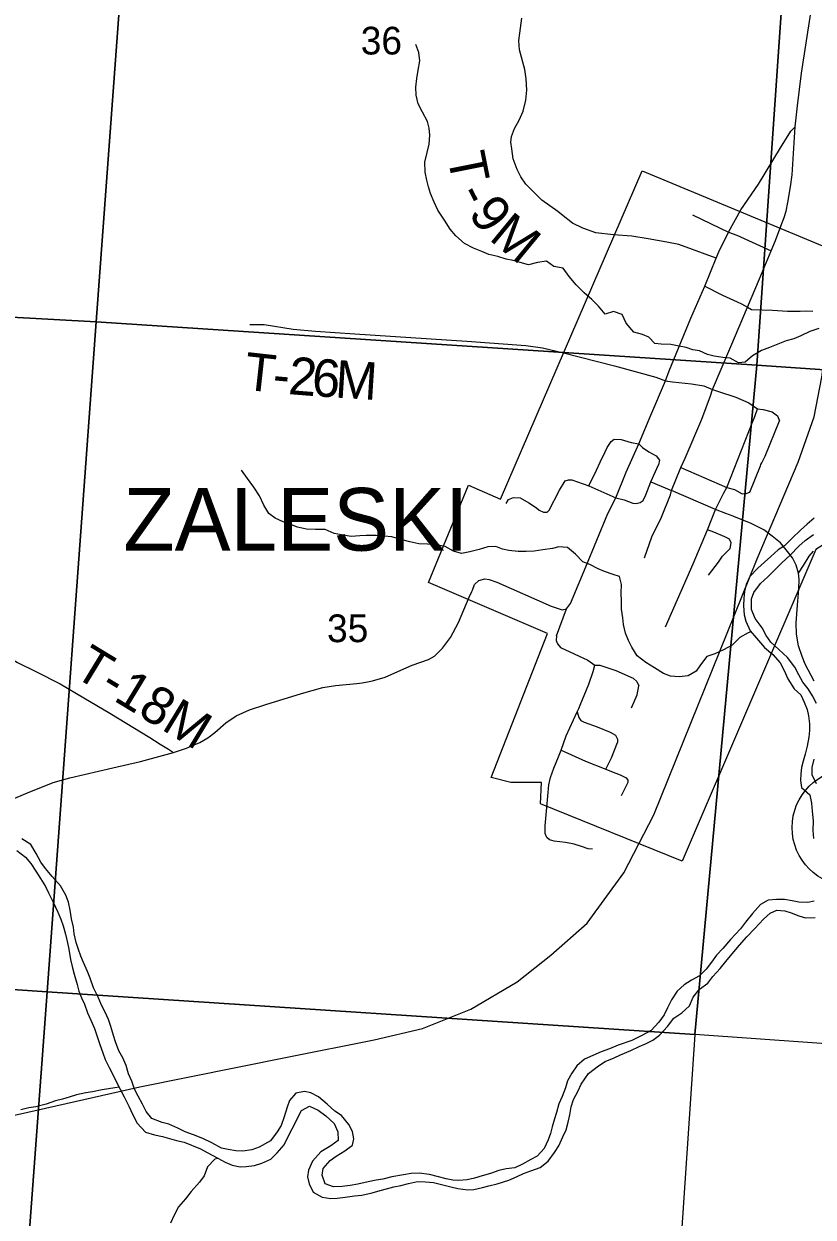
# Model space of a CAD drawing. Extents: x 0 to 34, y 0 to 22.
# Drawn here: x 26.642 to 27.834, y 16.59 to 18.393 of the extents above; entities that cross this region are included whole.
import ezdxf

# ---------------------------------------------------------------- set-up
doc = ezdxf.new("R2010")
doc.units = 0
for name, color, linetype in [('GM_X_City_Street', 7, 'Continuous'), ('GM_X_Corporation', 7, 'Continuous'), ('GM_X_Corporation_Text', 7, 'Continuous'), ('GM_X_Major_River', 7, 'Continuous'), ('GM_X_Minor_River', 7, 'Continuous'), ('GM_X_Rail_Line', 7, 'Continuous'), ('GM_X_Section', 7, 'Continuous'), ('GM_X_Section_Text', 7, 'Continuous'), ('GM_X_State_Route', 7, 'Continuous'), ('GM_X_Township_Road', 7, 'Continuous'), ('GM_X_Township_Road_Text', 7, 'Continuous'), ('SH_Data', 7, 'Continuous')]:
    doc.layers.add(name, color=color, linetype=linetype)

msp = doc.modelspace()

# ---------------------------------------------------------------- linework, layer by layer
at = {"layer": 'GM_X_City_Street'}
for p, q in [((27.5892, 17.7005), (27.6008, 17.7263)), ((27.4467, 17.4681), (27.4618, 17.5091))]:
    msp.add_line(p, q, dxfattribs=at)
for points in [[(27.5364, 17.6767), (27.552, 17.7153), (27.5708, 17.758), (27.5889, 17.8016), (27.6112, 17.8534), (27.6169, 17.8683), (27.6497, 17.9479), (27.6705, 17.9964), (27.688, 18.0388), (27.6918, 18.048), (27.7064, 18.078), (27.725, 18.1115)], [(27.6519, 18.104), (27.7064, 18.078), (27.7191, 18.0733), (27.7709, 18.0497)], [(27.6705, 17.9964), (27.6973, 17.9828), (27.7193, 17.9729), (27.7259, 17.9695)], [(27.7259, 17.9695), (27.7352, 17.9647), (27.7414, 17.9612), (27.7731, 17.96), (27.7954, 17.9585), (27.8148, 17.9588), (27.8244, 17.959), (27.8338, 17.9588)], [(27.5344, 17.876), (27.5966, 17.8591), (27.6112, 17.8534), (27.6221, 17.8517), (27.6507, 17.849), (27.669, 17.8457), (27.6824, 17.84), (27.6913, 17.8373), (27.7173, 17.8286), (27.7369, 17.8202), (27.7501, 17.8108), (27.7587, 17.81), (27.7724, 17.8063), (27.7803, 17.8004), (27.7833, 17.7929)], [(27.6115, 17.4818), (27.6531, 17.577), (27.6745, 17.6283), (27.6868, 17.6591), (27.6992, 17.6839), (27.7037, 17.6923), (27.7426, 17.7909), (27.7461, 17.7996), (27.7501, 17.8108)], [(27.7554, 17.7267), (27.7567, 17.7293), (27.7617, 17.7396), (27.7833, 17.7929)], [(27.4957, 17.6948), (27.5069, 17.7186), (27.5126, 17.7305), (27.5203, 17.7461), (27.5232, 17.7528), (27.5294, 17.7619)], [(27.5294, 17.7619), (27.5339, 17.7652), (27.5443, 17.7647), (27.5594, 17.7602), (27.5708, 17.758), (27.5768, 17.7528), (27.5862, 17.7463), (27.5971, 17.7401), (27.6021, 17.7337), (27.6008, 17.7263)], [(27.6345, 17.7225), (27.7037, 17.6923), (27.7154, 17.6891), (27.727, 17.6824), (27.733, 17.6829), (27.7384, 17.6851)], [(27.7384, 17.6851), (27.7546, 17.725), (27.7554, 17.7267)], [(27.3707, 17.6682), (27.3743, 17.6742), (27.3817, 17.6769), (27.3919, 17.6764), (27.405, 17.6692), (27.4164, 17.6613), (27.4206, 17.6578), (27.4271, 17.6549), (27.4325, 17.6551), (27.4357, 17.6578), (27.4511, 17.6883), (27.46, 17.7025), (27.4647, 17.7039), (27.4699, 17.7037), (27.4957, 17.6948), (27.5364, 17.6767)], [(27.5795, 17.5857), (27.5907, 17.6177), (27.6051, 17.6476), (27.6189, 17.6811), (27.6202, 17.6878)], [(27.6764, 17.5597), (27.6911, 17.5793), (27.6976, 17.5886), (27.7087, 17.6001), (27.7104, 17.6088), (27.7077, 17.614), (27.701, 17.6177), (27.6841, 17.6246), (27.6745, 17.6283)], [(27.4467, 17.4681), (27.4463, 17.4609), (27.4482, 17.4562), (27.4528, 17.4505), (27.494, 17.4311), (27.5048, 17.4239)], [(27.4321, 17.2087), (27.4353, 17.2429), (27.4374, 17.2539), (27.4427, 17.2682), (27.4496, 17.2851), (27.4539, 17.2951), (27.4612, 17.317), (27.4781, 17.3532), (27.4805, 17.3584), (27.4822, 17.3631), (27.4955, 17.3952), (27.5022, 17.414), (27.5048, 17.4239)], [(27.5048, 17.4239), (27.5122, 17.4237), (27.5362, 17.4157), (27.5624, 17.4039), (27.5679, 17.399), (27.5711, 17.3925)], [(27.5599, 17.3595), (27.5683, 17.3789), (27.5711, 17.3925)], [(27.4781, 17.3532), (27.4803, 17.3447), (27.4834, 17.3401), (27.4885, 17.3377), (27.5081, 17.3306), (27.5278, 17.3223), (27.5356, 17.3181), (27.5386, 17.3118), (27.5386, 17.3071)], [(27.4539, 17.2951), (27.4906, 17.2786), (27.5214, 17.2666), (27.5295, 17.263), (27.5426, 17.2579), (27.5517, 17.2537), (27.5546, 17.2501), (27.5544, 17.2465), (27.5445, 17.2262)], [(27.5214, 17.2666), (27.5299, 17.2839), (27.5386, 17.3071)]]:
    msp.add_lwpolyline(points, dxfattribs=at)
at = {"layer": 'GM_X_Corporation'}
msp.add_lwpolyline([(27.6365, 17.1274), (27.4226, 17.2144), (27.4242, 17.2466), (27.3779, 17.2466), (27.3482, 17.2539), (27.433, 17.4716), (27.2534, 17.5487), (27.314, 17.6957), (27.362, 17.6745), (27.5761, 18.1708), (28.0217, 17.9852), (27.9273, 17.6794), (27.9105, 17.6553), (27.8801, 17.6232), (27.8492, 17.6058), (27.8383, 17.5985)], close=True, dxfattribs=at)
at = {"layer": 'GM_X_Major_River'}
for points in [[(27.8356, 17.646), (27.8253, 17.6366), (27.8153, 17.6276), (27.8027, 17.6155), (27.7909, 17.6042), (27.7814, 17.5978), (27.7703, 17.5881), (27.7608, 17.5794), (27.7505, 17.5704), (27.7386, 17.5576), (27.7332, 17.5455), (27.7305, 17.5352), (27.7297, 17.525), (27.7292, 17.5132), (27.7303, 17.5), (27.7325, 17.4901)], [(27.7955, 17.4354), (27.7823, 17.4472), (27.7706, 17.4587), (27.7635, 17.4686), (27.7575, 17.4804), (27.7469, 17.4945), (27.7413, 17.5078), (27.7414, 17.5238), (27.7445, 17.5336), (27.7549, 17.5472), (27.7656, 17.557), (27.7774, 17.569), (27.7869, 17.5785), (27.7995, 17.5901), (27.8125, 17.6033), (27.8221, 17.612), (27.8346, 17.6214)], [(27.7325, 17.4901), (27.7392, 17.4756), (27.7486, 17.4645), (27.7607, 17.4504), (27.7735, 17.4397), (27.7844, 17.4271), (27.7904, 17.4157), (27.796, 17.4031), (27.8058, 17.3878), (27.8156, 17.3787), (27.8208, 17.368), (27.8253, 17.357), (27.8271, 17.3471), (27.8286, 17.3349), (27.8285, 17.3251), (27.8277, 17.3152), (27.8253, 17.3012), (27.8222, 17.2895), (27.8191, 17.2789), (27.8168, 17.269), (27.8156, 17.2595), (27.8151, 17.2497), (27.8169, 17.2387), (27.8294, 17.2279), (27.8316, 17.215), (27.833, 17.2032), (27.8341, 17.1888), (27.834, 17.174), (27.835, 17.1619)], [(27.8394, 17.3656), (27.8334, 17.3774), (27.8267, 17.3881), (27.8188, 17.398), (27.8128, 17.409), (27.8068, 17.4208), (27.7955, 17.4354)], [(27.8394, 17.2446), (27.8326, 17.2583), (27.8327, 17.2693), (27.8358, 17.2818)], [(27.1743, 16.6458), (27.1625, 16.6432), (27.1469, 16.6395), (27.1352, 16.6377), (27.123, 16.6363), (27.1097, 16.6357), (27.0972, 16.6399), (27.0928, 16.6532), (27.0944, 16.6631), (27.1047, 16.6755), (27.1142, 16.6819), (27.1272, 16.6902), (27.1386, 16.6984), (27.1406, 16.7083), (27.1384, 16.7193), (27.1331, 16.73), (27.1222, 16.7433), (27.112, 16.7498), (27.1003, 16.7605), (27.0875, 16.7716), (27.0758, 16.7774), (27.0663, 16.7794), (27.053, 16.7772), (27.0435, 16.7659), (27.04, 16.7561), (27.0353, 16.7413), (27.0311, 16.7284), (27.0249, 16.7186), (27.015, 16.705), (26.9979, 16.6953), (26.9864, 16.6916), (26.9728, 16.6894), (26.9622, 16.6899), (26.9508, 16.6918), (26.9406, 16.6938), (26.9262, 16.7023), (26.9126, 16.7084), (26.8986, 16.7139), (26.8861, 16.7189), (26.8751, 16.7243), (26.8615, 16.7301), (26.8513, 16.7328), (26.8358, 16.739), (26.8268, 16.7493), (26.8215, 16.7603), (26.8152, 16.7725), (26.8092, 16.7832), (26.8054, 16.795), (26.8006, 16.8064), (26.7969, 16.8189), (26.7916, 16.8304), (26.7856, 16.841), (26.7808, 16.8547), (26.7778, 16.8642), (26.7737, 16.8779), (26.77, 16.8886), (26.7652, 16.8996), (26.7595, 16.9103), (26.7547, 16.9221), (26.7476, 16.9362), (26.7424, 16.951), (26.7383, 16.9609), (26.7323, 16.9746), (26.7285, 16.9841), (26.7248, 16.994), (26.7215, 17.0047), (26.7185, 17.018), (26.7171, 17.0278), (26.7145, 17.0404), (26.7123, 17.0537), (26.7097, 17.0658), (26.7056, 17.0765), (26.6978, 17.0902), (26.685, 17.1043), (26.6748, 17.1166), (26.668, 17.1261), (26.6609, 17.139), (26.653, 17.1528), (26.6391, 17.1616)], [(26.6317, 17.1438), (26.645, 17.1338), (26.6529, 17.1239), (26.6604, 17.1125), (26.6675, 17.1014), (26.675, 17.0892), (26.6795, 17.0797), (26.6866, 17.0656), (26.6937, 17.0504), (26.6982, 17.0401), (26.7015, 17.0298), (26.7053, 17.0173), (26.7082, 17.0044), (26.7104, 16.9945), (26.713, 16.9789), (26.7152, 16.9683), (26.7181, 16.9569), (26.7226, 16.9413), (26.7255, 16.9314), (26.7293, 16.9211), (26.7338, 16.9116), (26.7382, 16.8987), (26.7435, 16.8876), (26.7491, 16.8747), (26.7524, 16.864), (26.7569, 16.8507), (26.7617, 16.8378), (26.7651, 16.8279), (26.7714, 16.8157), (26.7767, 16.8054), (26.7827, 16.7929), (26.7879, 16.783), (26.7939, 16.7715), (26.8014, 16.7563), (26.8063, 16.7456), (26.8137, 16.7319), (26.8258, 16.7182), (26.8394, 16.7143), (26.8515, 16.7115), (26.8625, 16.7088), (26.8731, 16.7057), (26.8845, 16.703), (26.9091, 16.6929), (26.9193, 16.6875), (26.9352, 16.6787), (26.9465, 16.6729), (26.9571, 16.6683), (26.9688, 16.6659), (26.9783, 16.6662), (26.9905, 16.6676), (27.0019, 16.6714), (27.0152, 16.6773), (27.0251, 16.6867), (27.0354, 16.6992), (27.0412, 16.7105), (27.0473, 16.723), (27.0616, 16.751), (27.0737, 16.7573), (27.087, 16.7515), (27.0983, 16.7431), (27.1111, 16.7313), (27.1163, 16.7187), (27.117, 16.7058), (27.106, 16.6975), (27.0907, 16.6885), (27.0781, 16.6742), (27.0723, 16.6606), (27.0708, 16.6507), (27.073, 16.6401), (27.0793, 16.6275), (27.0926, 16.6202), (27.1058, 16.6182), (27.1157, 16.6185)], [(27.8359, 17.067), (27.826, 17.0652), (27.8128, 17.0657), (27.8025, 17.0676), (27.7908, 17.0696), (27.779, 17.0697), (27.7665, 17.0687), (27.7547, 17.0623), (27.7425, 17.0487), (27.7322, 17.0355), (27.7245, 17.0253), (27.7096, 17.0091), (27.6978, 16.9959), (27.6882, 16.9854), (27.6809, 16.9752), (27.6725, 16.9646), (27.6626, 16.9545), (27.6504, 16.9477), (27.6394, 16.941), (27.6291, 16.9312), (27.6206, 16.9183), (27.6145, 16.9059), (27.6091, 16.8957), (27.6014, 16.8843), (27.5896, 16.8719), (27.5755, 16.864), (27.5603, 16.8569), (27.5398, 16.8495), (27.5268, 16.8443), (27.5143, 16.8395), (27.5014, 16.8342), (27.4892, 16.8286), (27.4773, 16.8185), (27.4697, 16.8075), (27.4635, 16.7958), (27.4604, 16.7852), (27.455, 16.772), (27.4504, 16.761), (27.4469, 16.7481), (27.4438, 16.7383), (27.4399, 16.7262), (27.4376, 16.7163), (27.4341, 16.7065), (27.428, 16.6933), (27.4173, 16.6819), (27.4078, 16.6767), (27.3952, 16.67), (27.3838, 16.6644), (27.3709, 16.6626), (27.3595, 16.6604), (27.3469, 16.6559), (27.3344, 16.6522), (27.323, 16.6489), (27.312, 16.6463), (27.2994, 16.6453), (27.29, 16.6457), (27.2801, 16.6477), (27.2684, 16.6508), (27.2547, 16.6543), (27.2392, 16.6563), (27.2274, 16.6556), (27.2157, 16.6535), (27.1978, 16.6506), (27.1845, 16.6472), (27.1743, 16.6458)], [(27.1157, 16.6185), (27.1278, 16.62), (27.1415, 16.6218), (27.1529, 16.6232), (27.1681, 16.6265), (27.1802, 16.6298), (27.1901, 16.6324), (27.2011, 16.6354), (27.2114, 16.6376), (27.2232, 16.6405), (27.2369, 16.6434), (27.249, 16.6433), (27.2611, 16.6421), (27.2869, 16.6355), (27.2975, 16.6331), (27.3126, 16.6311), (27.3221, 16.6318), (27.335, 16.6344), (27.3445, 16.6373), (27.3571, 16.6399), (27.3746, 16.6455), (27.3871, 16.6511), (27.397, 16.6555), (27.408, 16.66), (27.4221, 16.6648), (27.4343, 16.6742), (27.4439, 16.6874), (27.45, 16.6976), (27.4565, 16.7109), (27.4612, 16.7218), (27.4643, 16.7332), (27.4666, 16.7446), (27.4686, 16.7567), (27.4725, 16.7677), (27.4794, 16.7805), (27.484, 16.7907), (27.4951, 16.8066), (27.51, 16.8186), (27.5203, 16.825), (27.5339, 16.8306), (27.5435, 16.8351), (27.5591, 16.8418), (27.5716, 16.8474), (27.5811, 16.8515), (27.5922, 16.8571), (27.6024, 16.8646), (27.6143, 16.8778), (27.6239, 16.8902), (27.636, 16.8985), (27.6475, 16.909), (27.6529, 16.9223), (27.6625, 16.9344), (27.6754, 16.9434), (27.6827, 16.9536), (27.6938, 16.9656), (27.7026, 16.9762), (27.7121, 16.9875), (27.7232, 17.0007), (27.7343, 17.0131), (27.7461, 17.0259), (27.7591, 17.0399), (27.7694, 17.0489), (27.7793, 17.0534), (27.7914, 17.0525), (27.8013, 17.0494), (27.8126, 17.0452), (27.8229, 17.0421), (27.8373, 17.0427)]]:
    msp.add_lwpolyline(points, dxfattribs=at)
at = {"layer": 'GM_X_Minor_River'}
for points in [[(27.8429, 17.9325), (27.8293, 17.928), (27.8157, 17.9211), (27.8051, 17.9169), (27.7937, 17.9138), (27.7809, 17.9089), (27.7684, 17.9035), (27.7563, 17.8993), (27.7427, 17.891), (27.7317, 17.8815), (27.7215, 17.8803), (27.709, 17.8875), (27.6977, 17.8886), (27.6848, 17.8908), (27.6749, 17.8931), (27.6624, 17.8987), (27.6526, 17.9002), (27.6423, 17.9036), (27.6321, 17.9059), (27.6192, 17.9081), (27.6049, 17.9085), (27.595, 17.9096), (27.5863, 17.9194), (27.5764, 17.9232), (27.5635, 17.9269), (27.5521, 17.9406), (27.5457, 17.9538), (27.5328, 17.9583), (27.5203, 17.9541), (27.51, 17.9662), (27.5002, 17.9764), (27.4884, 17.9863), (27.4762, 17.9984), (27.4656, 18.0109), (27.4568, 18.0237), (27.4428, 18.026), (27.4315, 18.0339), (27.4182, 18.032), (27.4042, 18.0285), (27.3917, 18.0323), (27.3811, 18.0353), (27.3705, 18.0372), (27.358, 18.0413), (27.3444, 18.0443), (27.3341, 18.0485), (27.3212, 18.0537), (27.308, 18.0609), (27.2947, 18.0723), (27.2863, 18.0825), (27.2776, 18.0961), (27.2677, 18.1112), (27.262, 18.1234), (27.2566, 18.1366), (27.2532, 18.1465), (27.2509, 18.1563), (27.2486, 18.1688), (27.2481, 18.1836), (27.2515, 18.1984), (27.2545, 18.2109), (27.2556, 18.2246), (27.2544, 18.2352), (27.2517, 18.2451), (27.2445, 18.2594), (27.238, 18.2719), (27.2346, 18.2848), (27.2341, 18.297), (27.2356, 18.3099), (27.2378, 18.3228), (27.2401, 18.3368), (27.2389, 18.3493), (27.2343, 18.3614)], [(27.7404, 17.4742), (27.7361, 17.4727), (27.7233, 17.4655), (27.7119, 17.4541), (27.6987, 17.4468), (27.6859, 17.4407), (27.6738, 17.4369), (27.6643, 17.4244), (27.6576, 17.4145), (27.6455, 17.4076), (27.6318, 17.4061), (27.619, 17.4072), (27.6084, 17.411), (27.5947, 17.4196), (27.5814, 17.4279), (27.5685, 17.4378), (27.5602, 17.451), (27.5556, 17.4609), (27.551, 17.4722), (27.5479, 17.4851), (27.5468, 17.4954), (27.5448, 17.5083), (27.5448, 17.5211), (27.5444, 17.5325), (27.5447, 17.5458), (27.5416, 17.5579), (27.5322, 17.5605), (27.5193, 17.5651), (27.5094, 17.5692), (27.4969, 17.5756), (27.4867, 17.5798), (27.4753, 17.5915), (27.4635, 17.6013), (27.4503, 17.6024), (27.4404, 17.6001), (27.4261, 17.5978), (27.4132, 17.5959), (27.4011, 17.5955), (27.3886, 17.5955), (27.3746, 17.5969), (27.3651, 17.5992), (27.3553, 17.603), (27.3428, 17.6026), (27.3299, 17.5987), (27.3159, 17.5949), (27.303, 17.5926), (27.2909, 17.596), (27.2784, 17.6028), (27.2652, 17.6054), (27.2519, 17.6065), (27.2386, 17.6072), (27.225, 17.6102), (27.2114, 17.6136), (27.1981, 17.6174), (27.1864, 17.6185), (27.1743, 17.6196), (27.1595, 17.6199), (27.1497, 17.6191), (27.1364, 17.6184), (27.122, 17.6206), (27.1107, 17.6228), (27.0974, 17.6285), (27.083, 17.6285), (27.069, 17.6292), (27.0557, 17.6322), (27.0463, 17.6356), (27.0341, 17.6405), (27.022, 17.6461), (27.0121, 17.6529), (27.0049, 17.6654), (26.998, 17.6794), (26.9897, 17.6927), (26.9802, 17.7056), (26.971, 17.7184)], [(26.7863, 16.786), (26.7795, 16.7851), (26.7606, 16.7821), (26.7458, 16.779), (26.736, 16.7774), (26.722, 16.7748), (26.711, 16.7713), (26.7008, 16.7679), (26.6902, 16.7656), (26.6762, 16.7606), (26.6604, 16.7564), (26.6501, 16.7549), (26.6377, 16.7518)], [(26.9355, 16.6785), (26.9305, 16.6774), (26.9199, 16.666), (26.9147, 16.6524), (26.9075, 16.6425), (26.8951, 16.6284), (26.8864, 16.6174), (26.8759, 16.6053), (26.8695, 16.5927), (26.8638, 16.5806)]]:
    msp.add_lwpolyline(points, dxfattribs=at)
at = {"layer": 'GM_X_Rail_Line'}
msp.add_lwpolyline([(26.5786, 16.733), (26.6481, 16.7486), (26.8176, 16.7869), (27.0402, 16.8315), (27.1711, 16.8577), (27.2441, 16.875), (27.3175, 16.9041), (27.3875, 16.9452), (27.438, 16.9856), (27.4932, 17.0339), (27.5486, 17.1099), (27.5938, 17.1974), (27.7498, 17.5842), (27.8117, 17.7304), (27.8358, 17.7987), (27.8472, 17.8588), (27.856, 17.9255), (27.8667, 18.0165), (27.8787, 18.0627), (27.8912, 18.1011), (27.9122, 18.1517), (27.978, 18.2807), (28.2126, 18.7214)], dxfattribs=at)
at = {"layer": 'GM_X_Section'}
for points in [[(25.7909, 19.041), (25.8109, 19.0399), (26.8274, 18.9732), (26.7513, 17.9427), (25.7287, 17.9991)], [(26.8274, 18.9732), (27.8204, 18.905), (27.7492, 17.8771), (26.7513, 17.9427)], [(25.7287, 17.9991), (26.7513, 17.9427), (26.6773, 16.93), (25.6662, 16.9982)], [(26.7513, 17.9427), (27.7492, 17.8771), (27.6556, 16.8655), (26.6773, 16.93)], [(27.7492, 17.8771), (28.7165, 17.8103), (28.6406, 16.7957), (27.6556, 16.8655)], [(25.6662, 16.9982), (26.6773, 16.93), (26.6015, 15.9112), (25.5991, 15.9654)], [(27.6556, 16.8655), (27.6283, 16.4618), (27.6018, 16.0551), (27.5892, 15.8592), (26.6015, 15.9112), (26.6773, 16.93)]]:
    msp.add_lwpolyline(points, close=True, dxfattribs=at)
msp.add_lwpolyline([(28.7433, 18.1795), (28.7165, 17.8103), (27.7492, 17.8771), (27.8204, 18.905), (28.7909, 18.8364), (28.7636, 18.4595)], dxfattribs=at)
at = {"layer": 'GM_X_State_Route'}
for points in [[(27.7856, 18.0871), (27.7905, 18.1003), (27.7937, 18.1097), (27.7962, 18.1229), (27.8001, 18.1464), (27.8026, 18.1645), (27.8073, 18.2371), (27.8105, 18.2686), (27.8167, 18.318), (27.831, 18.4095)], [(27.753, 18.0072), (27.7709, 18.0497), (27.7776, 18.0654), (27.7856, 18.0871)], [(27.6794, 17.8306), (27.6824, 17.84), (27.7101, 17.9052), (27.7352, 17.9647), (27.753, 18.0072)], [(27.6202, 17.6878), (27.6345, 17.7225), (27.641, 17.7364), (27.6663, 17.7952), (27.6794, 17.8306)], [(27.3196, 17.5369), (27.3229, 17.5458), (27.3296, 17.5517), (27.3383, 17.554), (27.3448, 17.553), (27.3567, 17.549), (27.4385, 17.5128), (27.4551, 17.5076), (27.4618, 17.5091), (27.4677, 17.517), (27.491, 17.5721), (27.5242, 17.6529), (27.5364, 17.6767), (27.549, 17.6735), (27.5619, 17.6687), (27.5669, 17.6682), (27.5731, 17.6697), (27.5778, 17.6725), (27.5817, 17.6811), (27.5892, 17.7005), (27.6202, 17.6878)], [(27.7145, 17.6485), (27.7136, 17.6489), (27.7025, 17.6531), (27.6868, 17.6591), (27.6202, 17.6878)], [(27.8123, 17.5629), (27.8088, 17.5748), (27.8031, 17.5859), (27.7977, 17.5931), (27.785, 17.6085), (27.7726, 17.6189), (27.76, 17.6281), (27.7406, 17.638), (27.7145, 17.6485)], [(27.8356, 17.3998), (27.8224, 17.4253), (27.8177, 17.437), (27.8123, 17.4531), (27.8091, 17.4704), (27.8088, 17.4875), (27.8108, 17.5146), (27.8128, 17.5384), (27.813, 17.5532), (27.8123, 17.5629)], [(26.8681, 17.2917), (26.8877, 17.2986), (26.8993, 17.3034), (26.9082, 17.3068), (26.9204, 17.314), (26.9308, 17.3219), (26.9471, 17.3366), (26.963, 17.347), (26.9833, 17.3562), (27.0079, 17.3643), (27.0617, 17.3807), (27.0939, 17.3901), (27.113, 17.3928), (27.145, 17.3963), (27.1531, 17.3973), (27.1611, 17.3988), (27.169, 17.4003), (27.1878, 17.4057), (27.2069, 17.4144), (27.2287, 17.4236), (27.2535, 17.4325), (27.2625, 17.4375), (27.2746, 17.4494), (27.2868, 17.4655), (27.2987, 17.4883), (27.3148, 17.5265), (27.319, 17.5352), (27.3196, 17.5369)], [(26.6072, 17.2138), (26.6476, 17.2309), (26.6864, 17.2463), (26.7117, 17.2535), (26.7768, 17.2686), (26.8184, 17.2784), (26.8681, 17.2917)]]:
    msp.add_lwpolyline(points, dxfattribs=at)
at = {"layer": 'GM_X_Township_Road'}
for points in [[(27.4074, 18.1435), (27.4004, 18.1504), (27.393, 18.1618), (27.3873, 18.1727), (27.3812, 18.189), (27.3793, 18.2038), (27.3776, 18.2139), (27.3787, 18.2224), (27.3835, 18.2346), (27.3903, 18.2473), (27.3962, 18.2606), (27.4006, 18.2775), (27.4017, 18.2927), (27.4008, 18.3094), (27.3989, 18.3238), (27.3907, 18.3536), (27.3896, 18.3677), (27.3911, 18.3787), (27.3945, 18.4015)], [(27.725, 18.1115), (27.7515, 18.1504), (27.785, 18.2052), (27.8006, 18.2305), (27.8073, 18.2371)], [(27.4544, 18.1046), (27.4486, 18.1092), (27.4247, 18.1263), (27.4074, 18.1435)], [(27.688, 18.0388), (27.6315, 18.0595), (27.6131, 18.0627), (27.585, 18.068), (27.5607, 18.0718), (27.5326, 18.0739), (27.506, 18.0771), (27.4866, 18.0838), (27.471, 18.0918), (27.4544, 18.1046)], [(26.9836, 17.9385), (27.0052, 17.9385), (27.0491, 17.9313), (27.0829, 17.9283), (27.142, 17.9245)], [(27.142, 17.9245), (27.3112, 17.9135), (27.4006, 17.9068), (27.4255, 17.9034), (27.4572, 17.8954), (27.5344, 17.876)], [(27.8123, 17.5629), (27.8197, 17.5743), (27.8284, 17.5884), (27.8346, 17.5959)], [(26.6276, 17.4308), (26.6328, 17.4279), (26.6602, 17.414), (26.6971, 17.3955)], [(26.6971, 17.3955), (26.7331, 17.3742), (26.772, 17.3513), (26.8324, 17.3143), (26.8482, 17.3046), (26.8606, 17.2969), (26.8681, 17.2917)], [(27.5012, 17.1457), (27.4944, 17.1462), (27.4845, 17.1497), (27.4735, 17.1533), (27.4604, 17.1559), (27.4433, 17.1576), (27.4363, 17.1599), (27.4321, 17.1633), (27.4296, 17.1692), (27.4298, 17.1808), (27.4321, 17.2087)]]:
    msp.add_lwpolyline(points, dxfattribs=at)
at = {"layer": 'SH_Data'}
msp.add_circle((27.8907, 17.1784), 0.0883, dxfattribs=at)

# ---------------------------------------------------------------- texts
at = {"layer": 'GM_X_Corporation_Text'}
msp.add_text('ZALESKI', height=0.0947, rotation=0, dxfattribs=at).set_placement((26.7927, 17.5968))
at = {"layer": 'GM_X_Section_Text'}
for s, p in [('36', (27.1511, 18.3464)), ('35', (27.1002, 17.4585))]:
    msp.add_text(s, height=0.04186, rotation=0, dxfattribs=at).set_placement(p)
at = {"layer": 'GM_X_Township_Road_Text'}
for s, height, rotation, p in [('T', 0.0568, 281.3192, (27.2815, 18.1934)), ('-', 0.0568, 296.9783, (27.2954, 18.1358)), ('9', 0.0568, 307.608, (27.3121, 18.1053)), ('M', 0.0568, 320.528, (27.3432, 18.0675)), ('T', 0.0568, 353.6745, (26.9732, 17.8404)), ('2', 0.0568, 355.4795, (27.0406, 17.8334)), ('6', 0.0568, 356.0682, (27.0761, 17.8306)), ('M', 0.0568, 356.3452, (27.1113, 17.8282)), ('-', 0.0568, 354.7929, (27.0166, 17.8356)), ('T-18M', 0.05682, 328.7331, (26.7148, 17.4085))]:
    msp.add_text(s, height=height, rotation=rotation, dxfattribs=at).set_placement(p)

doc.saveas('drawing.dxf')
